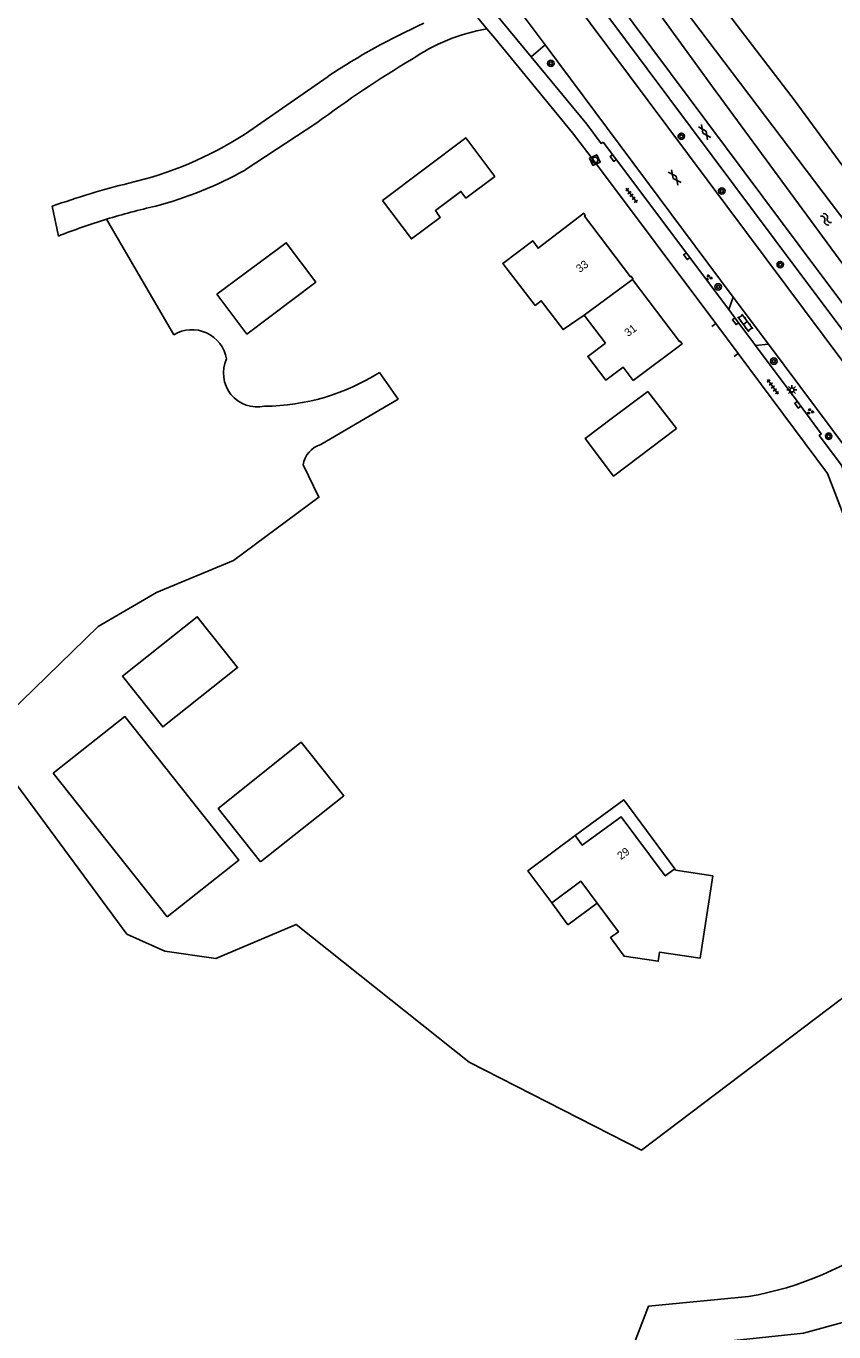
# Model space of a CAD drawing. Extents: x 136000 to 141014, y 402000 to 403500.
# Drawn here: x 137119.1 to 137220, y 402867.4 to 403030.5 of the extents above; entities that cross this region are included whole.
import ezdxf

# ---------------------------------------------------------------- set-up
doc = ezdxf.new("R2010")
doc.units = 0
for name, color, linetype in [('gg-afsc-draadraster', 7, 'Continuous'), ('gg-afsc-lijn draadraster', 7, 'Continuous'), ('gg-anno-huisnummerreeks BGT', 7, 'Continuous'), ('gg-bbg-bijgebouw', 7, 'Continuous'), ('gg-bbg-gedigitaliseerde bebouwing', 7, 'Continuous'), ('gg-bbg-gedigitaliseerde bijgebouw', 7, 'Continuous'), ('gg-bbg-hoofdgebouw', 7, 'Continuous'), ('gg-bbg-onder overbouw', 7, 'Continuous'), ('gg-bbg-open loods', 7, 'Continuous'), ('gg-bbg-pand overbouw', 7, 'Continuous'), ('gg-bbg-tussenscheiding', 7, 'Continuous'), ('gg-knt-bronhoudergrens', 7, 'Continuous'), ('gg-knt-verharding', 7, 'Continuous'), ('gg-kntw-bovenkant insteek waterloop', 7, 'Continuous'), ('gt-grn-groengrens', 7, 'Continuous'), ('gt-symb-boom', 7, 'Continuous'), ('gt-symb-gesloten verharding', 7, 'Continuous'), ('gt-symb-groenvak', 7, 'Continuous'), ('gt-symb-klinker verharding', 7, 'Continuous'), ('gt-symb-kolk', 7, 'Continuous'), ('gt-symb-lichtmast', 7, 'Continuous'), ('gt-symb-rioolschacht', 7, 'Continuous'), ('gt-symb-tegel verharding', 7, 'Continuous'), ('gt-symb-watersymbool', 7, 'Continuous')]:
    doc.layers.add(name, color=color, linetype=linetype)

# ---------------------------------------------------------------- blocks, each defined once
blk = doc.blocks.new('gt0-BOOM')
at = {"layer": 'gt-symb-boom'}
for radius in [0.4, 0.2]:
    blk.add_circle((0, 0), radius, dxfattribs=at)
blk = doc.blocks.new('gt0-GRVAK')
at = {"layer": 'gt-symb-groenvak'}
for p, q in [((-0.11, 0.19), (-0.23, 0.24)), ((-0.18, 0.15), (0.09, 0.15)), ((-0.09, 0.21), (-0.16, 0.32)), ((-0.05, 0.21), (-0.05, 0.39)), ((0, 0.21), (0.06, 0.32)), ((0.02, 0.19), (0.13, 0.24)), ((0.26, -0.05), (0.2, 0.06)), ((0.31, -0.05), (0.31, 0.13)), ((0.35, -0.05), (0.41, 0.06)), ((-0.24, -0.23), (-0.36, -0.18)), ((-0.32, -0.26), (-0.05, -0.26)), ((-0.23, -0.21), (-0.29, -0.1)), ((-0.18, -0.2), (-0.18, -0.02)), ((-0.14, -0.21), (-0.07, -0.1)), ((-0.12, -0.23), (0, -0.18)), ((0.24, -0.07), (0.12, -0.02)), ((0.17, -0.11), (0.44, -0.11)), ((0.37, -0.07), (0.49, -0.02))]:
    blk.add_line(p, q, dxfattribs=at)
blk = doc.blocks.new('gt0-KOLK')
at = {"layer": 'gt-symb-kolk'}
blk.add_lwpolyline([(0, 0), (0.38, 0), (0.38, 0.4), (-0.37, 0.4), (-0.37, 0), (0, 0)], dxfattribs=at)
blk = doc.blocks.new('gt0-LMAST')
at = {"layer": 'gt-symb-lichtmast'}
for p, q in [((-0.18, 0.17), (-0.45, 0.44)), ((0, 0.25), (0, 0.62)), ((0.17, 0.17), (0.44, 0.44)), ((-0.25, 0), (-0.63, 0)), ((-0.18, -0.18), (-0.45, -0.45)), ((0, -0.25), (0, -0.63)), ((0.44, -0.45), (0.17, -0.18)), ((0.25, 0), (0.62, 0))]:
    blk.add_line(p, q, dxfattribs=at)
blk.add_circle((0, 0), 0.25, dxfattribs=at)
blk = doc.blocks.new('gt0-TEG1')
at = {"layer": 'gt-symb-tegel verharding'}
for p, q in [((-1.12, 0), (1.12, 0)), ((-0.9, -0.25), (-0.9, 0.25)), ((-0.45, -0.25), (-0.45, 0.25)), ((0, -0.25), (0, 0.25)), ((0.45, -0.25), (0.45, 0.25)), ((0.9, -0.25), (0.9, 0.25))]:
    blk.add_line(p, q, dxfattribs=at)
blk = doc.blocks.new('gt0-KL1')
at = {"layer": 'gt-symb-klinker verharding'}
for p, q in [((-1.15, 0.3), (1.15, 0.3)), ((-1, -0.3), (-1, 0.3)), ((-0.5, 0.3), (-0.5, 0.45)), ((0, -0.3), (0, 0.3)), ((0.5, 0.3), (0.5, 0.45)), ((1, -0.3), (1, 0.3)), ((-1.15, -0.3), (1.15, -0.3)), ((-0.5, -0.45), (-0.5, -0.3)), ((0.5, -0.45), (0.5, -0.3))]:
    blk.add_line(p, q, dxfattribs=at)
blk = doc.blocks.new('gt0-WA')
at = {"layer": 'gt-symb-watersymbool'}
for centre, start, end in [((-0.32, 0.02), 28.0725, 151.9275), ((0.43, 0.42), 208.0725, 331.9275), ((-0.32, -0.43), 28.0725, 151.9275), ((0.43, -0.03), 208.0725, 331.9275)]:
    blk.add_arc(centre, 0.425, start, end, dxfattribs=at)
blk = doc.blocks.new('gt0-GESVH1')
at = {"layer": 'gt-symb-gesloten verharding'}
for p, q in [((-0.99, -0.26), (0.01, 0.24)), ((0.01, -0.26), (-0.99, 0.24)), ((0.01, 0.24), (1.01, -0.26)), ((1.01, 0.24), (0.01, -0.26))]:
    blk.add_line(p, q, dxfattribs=at)
blk = doc.blocks.new('gt0-RS')
at = {"layer": 'gt-symb-rioolschacht'}
blk.add_lwpolyline([(-0.5, -0.5), (0.5, -0.5), (0.5, 0.5), (-0.5, 0.5)], close=True, dxfattribs=at)
blk.add_circle((0, 0), 0.375, dxfattribs=at)

msp = doc.modelspace()

# ---------------------------------------------------------------- linework, layer by layer
at = {"layer": 'gg-afsc-draadraster'}
msp.add_lwpolyline([(137281.83, 402933.32), (137274.29, 402941.39), (137248.5, 402975.65), (137215.03, 403021.29), (137187.77, 403056.88), (137148.09, 403110.86), (137102.84, 403169.33), (137235.4, 403271.46), (137250.02, 403281.72)], dxfattribs=at)
at = {"layer": 'gg-afsc-lijn draadraster'}
msp.add_lwpolyline([(137281.83, 402933.32), (137274.29, 402941.39), (137248.5, 402975.65), (137215.03, 403021.29), (137187.77, 403056.88), (137148.09, 403110.86), (137102.84, 403169.33), (137235.4, 403271.46), (137250.49, 403282.05)], dxfattribs=at)
at = {"layer": 'gg-bbg-bijgebouw'}
msp.add_line((137196.74, 402984.86), (137200.31, 402980.25), dxfattribs=at)
for points in [[(137163.61, 403008.74), (137173.99, 403016.57), (137177.62, 403011.73), (137174.02, 403009.03), (137173.39, 403009.86), (137170.19, 403007.46), (137170.81, 403006.62), (137167.21, 403003.92), (137163.61, 403008.74)], [(137142.9, 402997.02), (137146.66, 402992.04), (137155.27, 402998.54), (137151.57, 403003.44), (137142.9, 402997.02)], [(137148.35, 402926.09), (137143.07, 402932.74), (137153.41, 402941.05), (137158.74, 402934.35), (137148.35, 402926.09)]]:
    msp.add_lwpolyline(points, dxfattribs=at)
at = {"layer": 'gg-bbg-gedigitaliseerde bebouwing'}
msp.add_lwpolyline([(137188.8, 402994.42), (137186.15, 402992.6), (137183.42, 402996.2), (137182.64, 402995.61)], dxfattribs=at)
at = {"layer": 'gg-bbg-gedigitaliseerde bijgebouw'}
msp.add_line((137136.71, 402919.22), (137122.47, 402937.16), dxfattribs=at)
for points in [[(137200.31, 402980.25), (137192.46, 402974.28), (137188.9, 402978.97), (137192.33, 402981.58), (137196.74, 402984.86)], [(137122.47, 402937.16), (137131.42, 402944.25), (137145.65, 402926.31), (137136.71, 402919.22)]]:
    msp.add_lwpolyline(points, dxfattribs=at)
at = {"layer": 'gg-bbg-hoofdgebouw'}
msp.add_line((137188.8, 402994.42), (137191.44, 402990.92), dxfattribs=at)
for points in [[(137182.64, 402995.61), (137178.64, 403000.87), (137182.36, 403003.7), (137183.03, 403002.77), (137188.72, 403007.14), (137188.92, 403006.86), (137188.83, 403006.79), (137194.58, 402999.18), (137194.66, 402999.25), (137194.86, 402998.98), (137194.78, 402998.91), (137194.81, 402998.87)], [(137194.92, 402986.24), (137201.02, 402990.82), (137200.76, 402991.17), (137200.67, 402991.1), (137194.81, 402998.87)], [(137194.92, 402986.24), (137193.65, 402987.91), (137191.49, 402986.27), (137189.23, 402989.25), (137191.44, 402990.92)], [(137187.65, 402929.38), (137181.75, 402924.99), (137184.73, 402920.98)], [(137203.28, 402914.05), (137204.84, 402924.33), (137200.21, 402925.04), (137200.1, 402925.2)], [(137203.28, 402914.05), (137198.19, 402914.79), (137198.03, 402913.68), (137193.77, 402914.3), (137192.08, 402916.63), (137193.05, 402917.35), (137190.39, 402920.93)]]:
    msp.add_lwpolyline(points, dxfattribs=at)
at = {"layer": 'gg-bbg-onder overbouw'}
for points in [[(137200.1, 402925.2), (137198.9, 402924.33), (137193.39, 402931.73), (137188.54, 402928.17), (137187.65, 402929.38)], [(137184.73, 402920.98), (137188.36, 402923.67), (137190.39, 402920.93)]]:
    msp.add_lwpolyline(points, dxfattribs=at)
at = {"layer": 'gg-bbg-open loods'}
msp.add_lwpolyline([(137131.12, 402949.31), (137136.15, 402942.96), (137145.49, 402950.37), (137140.46, 402956.71), (137131.12, 402949.31)], dxfattribs=at)
at = {"layer": 'gg-bbg-pand overbouw'}
for points in [[(137187.65, 402929.38), (137193.72, 402933.85), (137200.1, 402925.2)], [(137190.39, 402920.93), (137186.76, 402918.24), (137184.73, 402920.98)]]:
    msp.add_lwpolyline(points, dxfattribs=at)
at = {"layer": 'gg-bbg-tussenscheiding'}
msp.add_line((137188.8, 402994.42), (137194.81, 402998.87), dxfattribs=at)
at = {"layer": 'gg-knt-bronhoudergrens'}
for points in [[(137239.57, 402923.08), (137195.96, 402890.08), (137174.4, 402901.06), (137152.81, 402918.28), (137142.78, 402914.02), (137136.41, 402914.92), (137131.66, 402917.05), (137113.64, 402941.48)], [(137254.47, 402913.8), (137249.77, 402898.41), (137245.09, 402888.41), (137235.84, 402878.21), (137221.49, 402868.66), (137216.19, 402867.2), (137202.4, 402865.74), (137195.15, 402866.23), (137196.8, 402870.56), (137209.31, 402871.79)]]:
    msp.add_lwpolyline(points, dxfattribs=at)
msp.add_arc((137202.49, 402911.97), 40.76, 279.6395, 333.7778, dxfattribs=at)
at = {"layer": 'gg-knt-verharding'}
for p, q in [((137242.44, 402959.96), (137184.11, 403038.18)), ((137183.92, 403028.16), (137178.71, 403035.15)), ((137176.64, 403030.17), (137174.38, 403032.91)), ((137182.15, 403026.69), (137176.58, 403033.41)), ((137183.92, 403028.16), (137182.15, 403026.69)), ((137183.92, 403028.16), (137207.41, 402996.66)), ((137206.84, 402995.09), (137207.41, 402996.66)), ((137207.41, 402996.66), (137211.8, 402990.77)), ((137205.23, 402993.35), (137204.72, 402992.97)), ((137208.02, 402989.62), (137205.23, 402993.35)), ((137210.18, 402990.59), (137211.8, 402990.77)), ((137211.8, 402990.77), (137237.39, 402956.45)), ((137208.02, 402989.62), (137207.51, 402989.25))]:
    msp.add_line(p, q, dxfattribs=at)
for points in [[(137146.54, 403095.86), (137151.22, 403089.43), (137217.98, 403000), (137245.73, 402963.01)], [(137185.96, 403039.56), (137215.47, 403000), (137244.24, 402961.61)], [(137205.23, 402993.35), (137190.2, 403013.42), (137187.34, 403017.19), (137179.71, 403026.48), (137177.61, 403029), (137176.64, 403030.17)], [(137182.15, 403026.69), (137189.11, 403018.25), (137190.9, 403015.85), (137191.14, 403016), (137192.57, 403014.15), (137206.84, 402995.09)], [(137206.84, 402995.09), (137207.85, 402993.75), (137210.18, 402990.59)], [(137210.18, 402990.59), (137215.63, 402983.32), (137218.39, 402979.56), (137218.15, 402979.37), (137220.93, 402975.64), (137223.02, 402970.23), (137223.11, 402970.1), (137223.04, 402969.99)], [(137221.41, 402968.8), (137219.18, 402974.6), (137208.02, 402989.62)]]:
    msp.add_lwpolyline(points, dxfattribs=at)
at = {"layer": 'gg-kntw-bovenkant insteek waterloop'}
msp.add_line((137225.97, 403000), (137192.47, 403044.28), dxfattribs=at)
msp.add_lwpolyline([(137192.47, 403044.28), (137190.32, 403042.92), (137204.8, 403022.91), (137221.69, 403000)], dxfattribs=at)
at = {"layer": 'gt-grn-groengrens'}
for p, q in [((137156.8, 403024.24), (137146.37, 403016.99)), ((137155.4, 403018.43), (137146.43, 403012.54)), ((137122.32, 403008), (137123.1, 403004.28)), ((137129.11, 403006.39), (137137.52, 402991.95))]:
    msp.add_line(p, q, dxfattribs=at)
for points in [[(137155.87, 402978.24), (137165.54, 402983.91), (137163.21, 402987.24)], [(137113.64, 402941.48), (137128.09, 402955.48), (137135.35, 402959.74), (137144.98, 402963.75), (137155.65, 402971.65), (137153.68, 402975.69)]]:
    msp.add_lwpolyline(points, dxfattribs=at)
for centre, radius, start, end in [((137203.91, 402953.26), 85.2, 114.3671, 123.5778), ((137180.6, 403006.86), 23.64, 99.6413, 124.5254), ((137237.17, 402909.3), 136.36, 120.873, 126.845), ((137121.45, 403055.88), 46.19, 283.0886, 302.6489), ((137122.96, 403054.58), 48.15, 284.8078, 299.168), ((137157.03, 402910.33), 103.66, 104.0251, 109.5619), ((137153.69, 402926.69), 83.4, 102.763, 107.1415), ((137153.74, 402926.54), 83.56, 107.1427, 111.513), ((137139.78, 402988.2), 4.38, 9.5966, 121.0555), ((137147.98, 402987.18), 4.26, 155.6827, 282.028), ((137148.62, 403010.32), 27.3, 270.5074, 302.2959), ((137156.86, 402975.18), 3.22, 107.9358, 170.7803)]:
    msp.add_arc(centre, radius, start, end, dxfattribs=at)

# ---------------------------------------------------------------- block references
at = {"layer": 'gt-symb-boom'}
for p in [(137184.62, 403025.86), (137200.91, 403016.75), (137205.98, 403009.92), (137213.27, 403000.71), (137205.52, 402997.94), (137212.47, 402988.65), (137219.32, 402979.27)]:
    msp.add_blockref('gt0-BOOM', p, dxfattribs=at)
at = {"layer": 'gt-symb-gesloten verharding'}
for p, rotation in [((137203.82, 403017.25), 125.02487328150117), ((137200.09, 403011.62), -53.004102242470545)]:
    msp.add_blockref('gt0-GESVH1', p, dxfattribs=dict(at, rotation=rotation))
at = {"layer": 'gt-symb-groenvak'}
for p in [(137204.33, 402999.08), (137217, 402982.36)]:
    msp.add_blockref('gt0-GRVAK', p, dxfattribs=at)
at = {"layer": 'gt-symb-klinker verharding', "rotation": -53.290465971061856}
msp.add_blockref('gt0-KL1', (137208.91, 402993.43), dxfattribs=at)
at = {"layer": 'gt-symb-kolk'}
for p, rotation in [((137192.57, 403014.15), 127.7292698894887), ((137201.76, 403001.88), 126.86989764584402), ((137207.85, 402993.75), 127.0761203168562), ((137215.63, 402983.32), 126.86989764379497)]:
    msp.add_blockref('gt0-KOLK', p, dxfattribs=dict(at, rotation=rotation))
at = {"layer": 'gt-symb-lichtmast'}
msp.add_blockref('gt0-LMAST', (137214.74, 402985.05), dxfattribs=at)
at = {"layer": 'gt-symb-rioolschacht', "rotation": -64.53665493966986}
msp.add_blockref('gt0-RS', (137190.12, 403013.77), dxfattribs=at)
at = {"layer": 'gt-symb-tegel verharding'}
for p, rotation in [((137194.7, 403009.36), -53.7030410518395), ((137212.35, 402985.43), 125.43780146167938)]:
    msp.add_blockref('gt0-TEG1', p, dxfattribs=dict(at, rotation=rotation))
at = {"layer": 'gt-symb-watersymbool', "rotation": 133.01389341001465}
msp.add_blockref('gt0-WA', (137219.03, 403006.33), dxfattribs=at)

# ---------------------------------------------------------------- texts
at = {"layer": 'gg-anno-huisnummerreeks BGT'}
for s, rotation, p in [('33', 37.1, (137188.23, 402999.66)), ('31', 37.1, (137194.27, 402991.66)), ('29', 36.4, (137193.37, 402926.29))]:
    msp.add_text(s, height=1, rotation=rotation, dxfattribs=at).set_placement(p)

doc.saveas('drawing.dxf')
